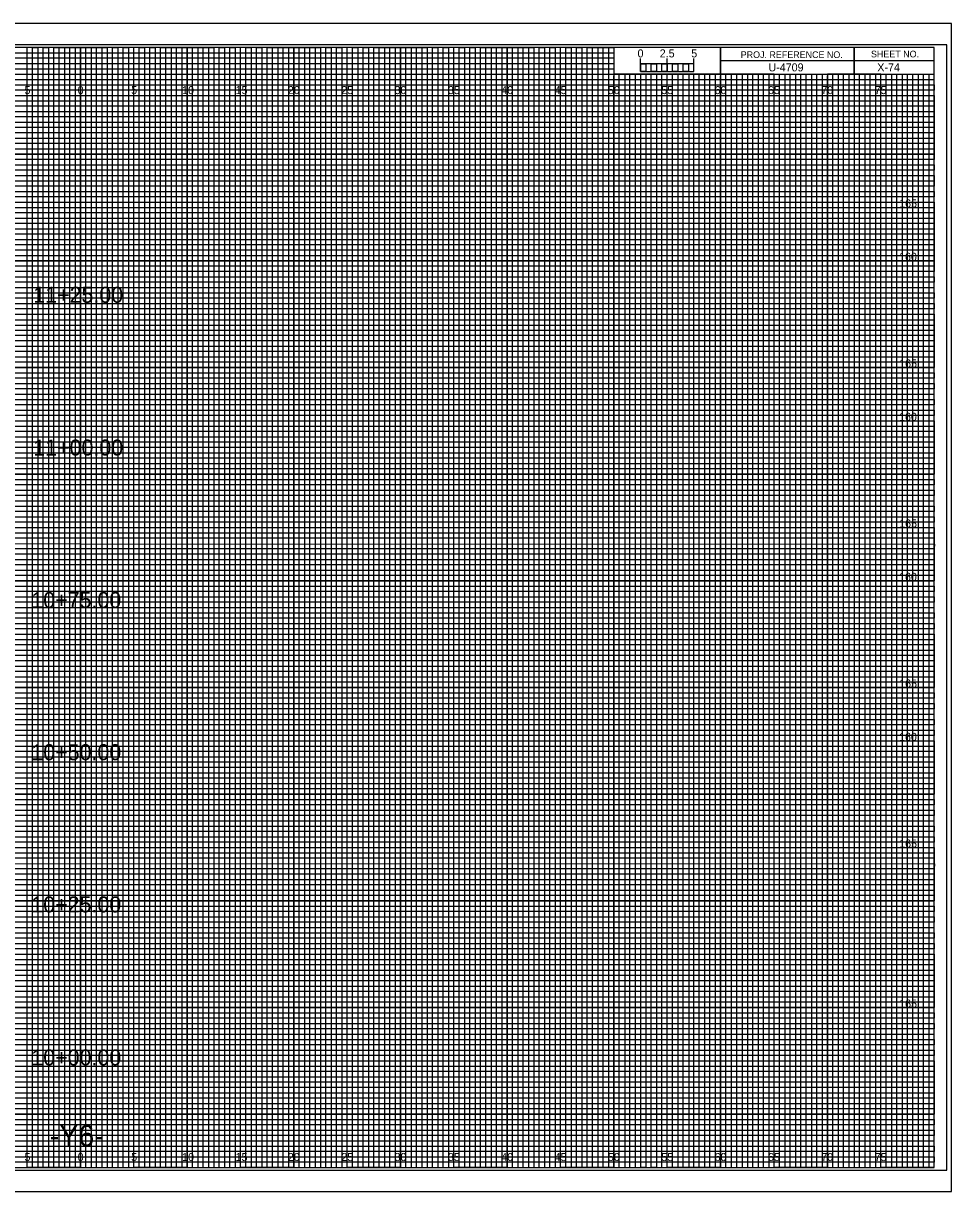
# Model space of a CAD drawing. Extents: x -7 to 162, y -2 to 107.
# Drawn here: x 74.6 to 161.7, y -2.3 to 107.3 of the extents above; entities that cross this region are included whole.
import ezdxf

# ---------------------------------------------------------------- set-up
doc = ezdxf.new("R2010")
doc.units = 0
for name, color, linetype in [('Prop CMT Conc Surface', 7, 'Continuous'), ('Prop CMT Pvmt Wedge Surface 1', 7, 'Continuous'), ('Prop CMT Pvmt Wedge Surface 2', 7, 'Continuous'), ('Prop XS Alignment Label', 7, 'Continuous'), ('Prop XS Bar Scale Labels', 7, 'Continuous'), ('Prop XS Ditch Standard Text', 7, 'Continuous'), ('Prop XS Elevation Labels', 7, 'Continuous'), ('Prop XS Hydro Elevations', 7, 'Continuous'), ('Prop XS Project Number', 7, 'Continuous'), ('Prop XS SE Text', 7, 'Continuous'), ('Prop XS Sheet Number', 7, 'Continuous'), ('Prop XS Side Slope Text', 7, 'Continuous'), ('Prop XS Station Labels', 7, 'Continuous'), ('Sheet Cutting Line CELL', 7, 'Continuous'), ('Sheet DOT Grid CELL', 7, 'Continuous'), ('Sheet Plot Border Inside CELL', 7, 'Continuous'), ('Sheet Plot Border Outside CELL', 7, 'Continuous')]:
    doc.layers.add(name, color=color, linetype=linetype)

msp = doc.modelspace()

# ---------------------------------------------------------------- linework, layer by layer
at = {"layer": 'Prop CMT Pvmt Wedge Surface 1'}
for p, q in [((132.5, 102.75), (132.5, 103.95)), ((132.5, 103.45), (132.5, 103.95)), ((135, 102.75), (135, 103.95)), ((137.5, 102.75), (137.5, 103.95)), ((137.5, 103.45), (137.5, 103.95))]:
    msp.add_line(p, q, dxfattribs=at)
for points in [[(137.5, 103.45), (132.5, 103.45), (132.5, 102.75), (137.5, 102.75)], [(132.5, 103.45), (133, 103.45), (133, 102.75), (132.5, 102.75)], [(133.5, 103.45), (134, 103.45), (134, 102.75), (133.5, 102.75)], [(134.5, 103.45), (135, 103.45), (135, 102.75), (134.5, 102.75)], [(135.5, 103.45), (136, 103.45), (136, 102.75), (135.5, 102.75)], [(136.5, 103.45), (137, 103.45), (137, 102.75), (136.5, 102.75)]]:
    msp.add_lwpolyline(points, close=True, dxfattribs=at)
at = {"layer": 'Prop CMT Pvmt Wedge Surface 2'}
for p, q in [((133.5, 102.5), (133, 102.5)), ((133, 102.5), (133, 0)), ((133.5, 0), (133.5, 102.5)), ((134.5, 102.5), (134, 102.5)), ((134, 102.5), (134, 0)), ((134.5, 0), (134.5, 102.5)), ((133, 0), (132.5, 0)), ((134, 0), (133.5, 0))]:
    msp.add_line(p, q, dxfattribs=at)
for points in [[(75, 0), (75.5, 0), (75.5, 105), (76, 105), (76, 0)], [(76, 0), (76.5, 0), (76.5, 105), (77, 105), (77, 0)], [(77.5, 0), (78, 0), (78, 105), (78.5, 105), (78.5, 0)], [(78.5, 0), (79, 0), (79, 105), (79.5, 105), (79.5, 0)], [(80, 0), (80.5, 0), (80.5, 105), (81, 105), (81, 0)], [(81, 0), (81.5, 0), (81.5, 105), (82, 105), (82, 0)], [(82.5, 0), (83, 0), (83, 105), (83.5, 105), (83.5, 0)], [(83.5, 0), (84, 0), (84, 105), (84.5, 105), (84.5, 0)], [(85, 0), (85.5, 0), (85.5, 105), (86, 105), (86, 0)], [(86, 0), (86.5, 0), (86.5, 105), (87, 105), (87, 0)], [(87.5, 0), (88, 0), (88, 105), (88.5, 105), (88.5, 0)], [(88.5, 0), (89, 0), (89, 105), (89.5, 105), (89.5, 0)], [(90, 0), (90.5, 0), (90.5, 105), (91, 105), (91, 0)], [(91, 0), (91.5, 0), (91.5, 105), (92, 105), (92, 0)], [(92.5, 0), (93, 0), (93, 105), (93.5, 105), (93.5, 0)], [(93.5, 0), (94, 0), (94, 105), (94.5, 105), (94.5, 0)], [(95, 0), (95.5, 0), (95.5, 105), (96, 105), (96, 0)], [(96, 0), (96.5, 0), (96.5, 105), (97, 105), (97, 0)], [(97.5, 0), (98, 0), (98, 105), (98.5, 105), (98.5, 0)], [(98.5, 0), (99, 0), (99, 105), (99.5, 105), (99.5, 0)], [(100, 0), (100.5, 0), (100.5, 105), (101, 105), (101, 0)], [(101, 0), (101.5, 0), (101.5, 105), (102, 105), (102, 0)], [(102.5, 0), (103, 0), (103, 105), (103.5, 105), (103.5, 0)], [(103.5, 0), (104, 0), (104, 105), (104.5, 105), (104.5, 0)], [(105, 0), (105.5, 0), (105.5, 105), (106, 105), (106, 0)], [(106, 0), (106.5, 0), (106.5, 105), (107, 105), (107, 0)], [(107.5, 0), (108, 0), (108, 105), (108.5, 105), (108.5, 0)], [(108.5, 0), (109, 0), (109, 105), (109.5, 105), (109.5, 0)], [(110, 0), (110.5, 0), (110.5, 105), (111, 105), (111, 0)], [(111, 0), (111.5, 0), (111.5, 105), (112, 105), (112, 0)], [(112.5, 0), (113, 0), (113, 105), (113.5, 105), (113.5, 0)], [(113.5, 0), (114, 0), (114, 105), (114.5, 105), (114.5, 0)], [(115, 0), (115.5, 0), (115.5, 105), (116, 105), (116, 0)], [(116, 0), (116.5, 0), (116.5, 105), (117, 105), (117, 0)], [(117.5, 0), (118, 0), (118, 105), (118.5, 105), (118.5, 0)], [(118.5, 0), (119, 0), (119, 105), (119.5, 105), (119.5, 0)], [(120, 0), (120.5, 0), (120.5, 105), (121, 105), (121, 0)], [(121, 0), (121.5, 0), (121.5, 105), (122, 105), (122, 0)], [(122.5, 0), (123, 0), (123, 105), (123.5, 105), (123.5, 0)], [(123.5, 0), (124, 0), (124, 105), (124.5, 105), (124.5, 0)], [(125, 0), (125.5, 0), (125.5, 105), (126, 105), (126, 0)], [(126, 0), (126.5, 0), (126.5, 105), (127, 105), (127, 0)], [(127.5, 0), (128, 0), (128, 105), (128.5, 105), (128.5, 0)], [(128.5, 0), (129, 0), (129, 105), (129.5, 105), (129.5, 0)], [(130, 0), (130.5, 0), (130.5, 102.5), (131.01, 102.5), (131.01, 0)], [(131, 0), (131.5, 0), (131.5, 102.5), (132, 102.5), (132, 0)], [(135, 0), (135.49, 0), (135.49, 102.5), (136, 102.5), (136, 0)], [(136, 0), (136.5, 0), (136.5, 102.5), (137.03, 102.5), (137.03, 0)], [(137.5, 0), (138, 0), (138, 102.5), (138.5, 102.5), (138.5, 0)], [(138.5, 0), (139, 0), (139, 102.5), (139.5, 102.5), (139.5, 0)], [(140, 0), (140.5, 0), (140.5, 102.5), (141, 102.5), (141, 0)], [(141, 0), (141.5, 0), (141.5, 102.5), (142, 102.5), (142, 0)], [(142.5, 0), (143, 0), (143, 102.5), (143.5, 102.5), (143.5, 0)], [(143.5, 0), (144, 0), (144, 102.5), (144.5, 102.5), (144.5, 0)], [(145, 0), (145.5, 0), (145.5, 102.5), (146, 102.5), (146, 0)], [(146, 0), (146.5, 0), (146.5, 102.5), (147, 102.5), (147, 0)], [(147.5, 0), (148, 0), (148, 102.5), (148.5, 102.5), (148.5, 0)], [(148.5, 0), (149, 0), (149, 102.5), (149.5, 102.5), (149.5, 0)], [(150, 0), (150.5, 0), (150.5, 102.5), (151, 102.5), (151, 0)], [(151, 0), (151.5, 0), (151.5, 102.5), (152, 102.5), (152, 0)], [(152.5, 0), (153, 0), (153, 102.5), (153.5, 102.5), (153.5, 0)], [(153.5, 0), (154, 0), (154, 102.5), (154.5, 102.5), (154.5, 0)], [(155, 0), (155.5, 0), (155.5, 102.5), (156, 102.5), (156, 0)], [(156, 0), (156.5, 0), (156.5, 102.5), (157, 102.5), (157, 0)], [(157.5, 0), (158, 0), (158, 102.5), (158.5, 102.5), (158.5, 0)], [(158.5, 0), (159, 0), (159, 102.5), (159.5, 102.5), (159.5, 0)]]:
    msp.add_lwpolyline(points, dxfattribs=at)
at = {"layer": 'Prop XS Ditch Standard Text'}
for p, q in [((0, 104.5), (130, 104.5)), ((130, 104.5), (130, 103.99)), ((130, 103.99), (0, 103.99)), ((0, 103.5), (130, 103.5)), ((130, 102.95), (0, 102.95)), ((130, 103.5), (130, 102.95)), ((0, 102), (160, 102))]:
    msp.add_line(p, q, dxfattribs=at)
for points in [[(0, 101.5), (135, 101.5), (160, 101.5), (160, 101), (0, 101)], [(0, 100.5), (160, 100.5), (160, 99.5), (0, 99.5)], [(0, 99), (160, 99), (160, 98.5), (0, 98.49)], [(0, 98), (160, 98), (160, 97), (0, 97)], [(0, 96.5), (160, 96.5), (160, 96), (0, 96)], [(0, 95.5), (160, 95.5), (160, 94.5), (0, 94.5)], [(0, 94), (160, 94), (160, 93.5), (0, 93.5)], [(0, 93), (160, 93), (160, 92), (0, 92)], [(0, 91.5), (160, 91.5), (160, 91), (0, 91)], [(0, 90.5), (160, 90.5), (160, 89.5), (0, 89.5)], [(0, 89), (160, 89), (160, 88.5), (0, 88.5)], [(0, 88), (160, 88), (160, 86.98), (160, 86.5), (160, 86), (0, 86)], [(0, 87), (160, 87), (160, 86.5), (0, 86.5)], [(0, 85.5), (160, 85.5), (160, 84.5), (0, 84.52)], [(0, 84.52), (160, 84.5), (160, 84), (0, 84)], [(0, 83.5), (160, 83.5), (160, 83), (0, 83)], [(0, 82), (160, 82), (160, 81.5), (0, 81.5)], [(0, 81), (160, 81), (160, 80.5), (0, 80.5)], [(-0.04, 79.45), (160, 79.45), (160, 78.94), (-0.04, 78.94)], [(0, 78.5), (160, 78.5), (160, 78), (0, 78)], [(0, 77), (160, 77), (160, 76.5), (0, 76.5)], [(0, 76), (160, 76), (160, 75.5), (0, 75.5)], [(0, 74.5), (160, 74.5), (160, 74), (0, 74)], [(0, 73.5), (160, 73.5), (160, 73), (0, 73)], [(0, 72), (160, 72), (160, 71.5), (0, 71.5)], [(0, 71), (160, 71), (160, 70.5), (0, 70.5)], [(0, 69.5), (160, 69.5), (160, 68.99), (0, 69)], [(0, 68.5), (160, 68.5), (160, 68), (0, 68)], [(0, 67), (160, 67), (160, 66.5), (0, 66.5)], [(0, 66), (160, 66), (160, 65.5), (0, 65.5)], [(0, 64.5), (160, 64.5), (160, 64), (0, 64)], [(0, 63.5), (160, 63.5), (160, 63), (0, 63)], [(0, 62), (160, 62), (160, 61.5), (0, 61.5)], [(0, 61), (160, 61), (160, 60.5), (0, 60.5)], [(0, 59.5), (160, 59.5), (160, 59), (0, 59)], [(0, 58.5), (160.03, 58.45), (160, 58), (0, 58)], [(0, 57), (160, 57), (160, 56.5), (0, 56.5)], [(0, 56), (160, 56), (160, 55.5), (0, 55.5)], [(0, 54.5), (160, 54.5), (160, 54), (0, 54)], [(0, 53.5), (160, 53.5), (160, 53), (0, 53)], [(0, 52), (160, 52), (160, 51.5), (0, 51.5)], [(0, 51), (160, 51), (160, 50.5), (0, 50.5)], [(0, 49.5), (160, 49.5), (160, 49), (0, 49)], [(0, 48.5), (160, 48.5), (160, 48), (0, 48)], [(0, 47), (160, 47), (160, 46.5), (0, 46.5)], [(0, 46), (160, 46), (160, 45.5), (0, 45.5)], [(0, 44.5), (160, 44.5), (160, 44), (0, 44)], [(0, 43.5), (160, 43.5), (160, 43), (0, 43)], [(0, 42), (160, 42), (160, 41.5), (0, 41.5)], [(0, 41), (160, 41), (160, 40.5), (0, 40.5)], [(0, 39.5), (160, 39.5), (160, 38.99), (0, 39)], [(0, 38.5), (160, 38.5), (160, 38), (0, 38)], [(0, 37), (160, 37), (160, 36.5), (0, 36.5)], [(0, 36), (160, 36), (160, 35.5), (0, 35.5)], [(0, 34.5), (160, 34.5), (160, 34), (0, 34)], [(0, 33.5), (160, 33.5), (160, 33), (0, 33)], [(0, 32), (160, 32), (160, 31.5), (0, 31.5)], [(0, 31), (160, 31), (160, 30.5), (0, 30.5)], [(0, 29.5), (160, 29.5), (160, 29), (0, 29)], [(0, 28.5), (160.03, 28.46), (160, 28), (0, 28)], [(0, 27), (160, 27), (160, 26.5), (0, 26.5)], [(0, 26), (160, 26), (160, 25.5), (0, 25.5)], [(0, 24.5), (160, 24.5), (160, 24), (0, 24)], [(0, 23.5), (160, 23.5), (160, 23), (0, 23)], [(0, 22), (160, 22), (160, 21.5), (0, 21.5)], [(0, 21), (160, 21), (160, 20.5), (0, 20.5)], [(0, 19.5), (160, 19.5), (160, 19), (0, 19)], [(0, 18.5), (160, 18.5), (160, 18), (0, 18)], [(0, 17), (160, 17), (160, 16.5), (0, 16.5)], [(0, 16), (160, 16), (160, 15.5), (0, 15.5)], [(0, 14.5), (160, 14.5), (160, 14), (0, 14)], [(0, 13.5), (160, 13.5), (160, 13), (0, 13)], [(0, 12), (160, 12), (160, 11.5), (0, 11.5)], [(0, 11), (160, 11), (160, 10.5), (0, 10.5)], [(0, 9.5), (160, 9.5), (160, 9), (0, 9)], [(0, 8.5), (160, 8.5), (160, 8), (0, 8)], [(0, 7), (160, 7), (160, 6.5), (0, 6.5)], [(0, 6), (160, 6), (160, 5.5), (0, 5.5)], [(0, 4.5), (160, 4.5), (160, 4), (0, 4)], [(0, 3.5), (160, 3.5), (160, 3), (0, 3)], [(0, 2), (160, 2), (160, 1.5), (0, 1.5)], [(0, 1), (160, 1), (160, 0.5), (0, 0.5)]]:
    msp.add_lwpolyline(points, dxfattribs=at)
at = {"layer": 'Prop XS Hydro Elevations'}
for p, q in [((152.5, 105), (152.5, 102.5)), ((152.5, 102.5), (152.5, 105)), ((160, 103.75), (140, 103.75)), ((140, 103.75), (140, 102.5)), ((140, 102.5), (160, 102.5))]:
    msp.add_line(p, q, dxfattribs=at)
for points in [[(160, 105), (0, 105), (0, 0), (160, 0)], [(140, 105), (130, 105), (130, 102.52), (140, 102.52)], [(160, 105), (140, 105), (140, 102.5), (160, 102.5)]]:
    msp.add_lwpolyline(points, close=True, dxfattribs=at)
at = {"layer": 'Prop XS SE Text'}
for points in [[(72.5, 0), (77.5, 0), (77.5, 105), (82.5, 105), (82.5, 0), (87.5, 0), (87.5, 105), (92.5, 105), (92.5, 0), (97.5, 0), (97.5, 105), (102.5, 105), (102.5, 0), (107.5, 0), (107.5, 105), (112.5, 105), (112.5, 0), (117.5, 0), (117.5, 105), (122.5, 105), (122.5, 0), (127.5, 0), (127.5, 105), (129.97, 105), (130, 105), (130, 102.5), (132.5, 102.5), (132.5, 0), (137.5, 0), (137.5, 102.5), (142.5, 102.5), (142.5, 0), (147.5, 0), (147.5, 102.5), (152.5, 102.5), (152.5, 0), (157.5, 0), (157.5, 102.5)], [(0, 102.5), (137.5, 102.5)], [(0, 92.5), (160, 92.5), (160, 97.5), (0, 97.5)], [(0, 82.5), (160, 82.5), (160, 87.5), (0, 87.5)], [(0, 72.5), (160, 72.5), (160, 77.5), (0, 77.5)], [(0, 62.5), (160, 62.5), (160, 67.5), (0, 67.5)], [(0, 52.5), (160, 52.5), (160, 57.5), (0, 57.5)], [(0, 42.5), (160, 42.5), (160, 47.5), (0, 47.5)], [(0, 32.5), (160, 32.5), (160, 37.5), (0, 37.5)], [(0, 22.5), (160, 22.5), (160, 27.5), (0, 27.5)], [(0, 12.5), (160, 12.5), (160, 17.5), (0, 17.5)], [(0, 2.5), (160, 2.5), (160, 7.5), (0, 7.5)]]:
    msp.add_lwpolyline(points, dxfattribs=at)
at = {"layer": 'Prop XS Side Slope Text'}
for p, q in [((75, 105), (70, 105)), ((75, 0), (75, 105)), ((85, 105), (80, 105)), ((80, 105), (80, 0)), ((85, 0), (85, 105)), ((95, 105), (90, 105)), ((90, 105), (90, 0)), ((95, 0), (95, 105)), ((105, 105), (100, 105)), ((100, 105), (100, 0)), ((105, 0), (105, 105)), ((115, 105), (110, 105)), ((110, 105), (110, 0)), ((115, 0), (115, 105)), ((125, 105), (120, 105)), ((120, 105), (120, 0)), ((125, 0), (125, 105)), ((130, 105), (130, 0)), ((135, 0), (135, 102.5)), ((145, 102.5), (140, 102.5)), ((140, 102.5), (140, 0)), ((145, 0), (145, 102.5)), ((155, 102.5), (150, 102.5)), ((150, 102.5), (150, 0)), ((155, 0), (155, 102.5)), ((80, 0), (75, 0)), ((90, 0), (85, 0)), ((100, 0), (95, 0)), ((110, 0), (105, 0)), ((120, 0), (115, 0)), ((130, 0), (125, 0)), ((140, 0), (135, 0)), ((150, 0), (145, 0)), ((160, 0), (155, 0)), ((160, 0), (160, 0))]:
    msp.add_line(p, q, dxfattribs=at)
for points in [[(0, 100), (160, 100), (160, 95), (0, 95)], [(0, 90), (160, 90), (160, 85), (0, 85)], [(0, 80), (160, 80), (160, 75), (0, 75)], [(0, 70), (160, 70), (160, 65), (0, 65)], [(0, 60), (160, 60), (160, 55), (0, 55)], [(0, 50), (160, 50), (160, 45), (0, 45)], [(0, 40), (160, 40), (160, 35), (0, 35)], [(0, 30), (160, 30), (160, 25), (0, 25)], [(0, 20), (160, 20), (160, 15), (0, 15)], [(0, 10), (160, 10), (160, 5), (0, 5)]]:
    msp.add_lwpolyline(points, dxfattribs=at)
at = {"layer": 'Sheet Cutting Line CELL'}
for p, q in [((161.65, 107.25), (-6.7, 107.25)), ((-6.7, -2.25), (161.65, -2.25))]:
    msp.add_line(p, q, dxfattribs=at)
at = {"layer": 'Sheet DOT Grid CELL'}
for p, q in [((75, 0), (75, 105)), ((80, 0), (80, 105)), ((85, 0), (85, 105)), ((90, 0), (90, 105)), ((95, 0), (95, 105)), ((100, 0), (100, 105)), ((105, 0), (105, 105)), ((110, 0), (110, 105)), ((115, 0), (115, 105)), ((120, 0), (120, 105)), ((125, 0), (125, 105)), ((130, 0), (130, 102.34)), ((135, 0), (135, 102.34)), ((140, 0), (140, 102.34)), ((145, 0), (145, 102.34)), ((150, 0), (150, 102.34)), ((155, 0), (155, 102.34)), ((0, 100), (160, 100)), ((0, 95), (160, 95)), ((0, 90), (160, 90)), ((0, 85), (160, 85)), ((0, 80), (160, 80)), ((0, 75), (160, 75)), ((0, 70), (160, 70)), ((0, 65), (160, 65)), ((0, 60), (160, 60)), ((0, 55), (160, 55)), ((0, 50), (160, 50)), ((0, 45), (160, 45)), ((0, 40), (160, 40)), ((0, 35), (160, 35)), ((0, 30), (160, 30)), ((0, 25), (160, 25)), ((0, 20), (160, 20)), ((0, 15), (160, 15)), ((0, 10), (160, 10)), ((0, 5), (160, 5))]:
    msp.add_line(p, q, dxfattribs=at)
at = {"layer": 'Sheet Plot Border Inside CELL'}
msp.add_lwpolyline([(-5.4, -0.25), (161.2, -0.25), (161.2, 105.25), (-5.4, 105.25)], close=True, dxfattribs=at)
at = {"layer": 'Sheet Plot Border Outside CELL'}
msp.add_lwpolyline([(-6.7, -2.25), (161.65, -2.25), (161.65, 107.25), (-6.7, 107.25)], close=True, dxfattribs=at)

# ---------------------------------------------------------------- texts
at = {"layer": 'Prop CMT Conc Surface'}
for s, p in [('5', (74.74, 100.62)), ('0', (79.73, 100.62)), ('0', (79.73, 100.62)), ('5', (84.74, 100.62)), ('10', (89.52, 100.62)), ('15', (94.53, 100.62)), ('20', (99.43, 100.62)), ('25', (104.44, 100.62)), ('30', (109.43, 100.62)), ('35', (114.44, 100.62)), ('40', (119.43, 100.62)), ('45', (124.44, 100.62)), ('50', (129.43, 100.62)), ('55', (134.44, 100.62)), ('60', (139.43, 100.62)), ('65', (144.44, 100.62)), ('70', (149.43, 100.62)), ('75', (154.44, 100.62)), ('5', (74.74, 0.62)), ('0', (79.73, 0.62)), ('0', (79.73, 0.62)), ('5', (84.74, 0.62)), ('10', (89.52, 0.62)), ('15', (94.53, 0.62)), ('20', (99.43, 0.62)), ('25', (104.44, 0.62)), ('30', (109.43, 0.62)), ('35', (114.44, 0.62)), ('40', (119.43, 0.62)), ('45', (124.44, 0.62)), ('50', (129.43, 0.62)), ('55', (134.44, 0.62)), ('60', (139.43, 0.62)), ('65', (144.44, 0.62)), ('70', (149.43, 0.62)), ('75', (154.44, 0.62))]:
    msp.add_text(s, height=0.75, dxfattribs=at).set_placement(p)
at = {"layer": 'Prop CMT Pvmt Wedge Surface 1'}
msp.add_text('0', height=0.75, dxfattribs=at).set_placement((132.21, 104.06))
at = {"layer": 'Prop XS Alignment Label'}
msp.add_text('-Y6-', height=2, dxfattribs=at).set_placement((77.12, 2))
at = {"layer": 'Prop XS Bar Scale Labels'}
for s, p in [('2.5', (134.29, 104.06)), ('5', (137.24, 104.06))]:
    msp.add_text(s, height=0.75, dxfattribs=at).set_placement(p)
at = {"layer": 'Prop XS Elevation Labels'}
for s, p in [('165', (156.73, 90)), ('160', (156.72, 85)), ('165', (156.73, 75)), ('160', (156.72, 70)), ('165', (156.73, 60)), ('160', (156.72, 55)), ('165', (156.73, 45)), ('160', (156.72, 40)), ('165', (156.73, 30)), ('165', (156.73, 15))]:
    msp.add_text(s, height=0.75, dxfattribs=at).set_placement(p)
at = {"layer": 'Prop XS Hydro Elevations'}
for s, p in [('PROJ. REFERENCE NO.', (141.88, 104)), ('SHEET NO.', (154.09, 104.06))]:
    msp.add_text(s, height=0.625, dxfattribs=at).set_placement(p)
at = {"layer": 'Prop XS Project Number'}
msp.add_text('U-4709', height=0.75, dxfattribs=at).set_placement((144.48, 102.75))
at = {"layer": 'Prop XS Sheet Number'}
msp.add_text('X-74', height=0.75, dxfattribs=at).set_placement((154.68, 102.75))
at = {"layer": 'Prop XS Station Labels'}
for s, p in [('11+25.00', (75.57, 81.06)), ('11+00.00', (75.57, 66.74)), ('10+75.00', (75.39, 52.45)), ('10+50.00', (75.39, 38.19)), ('10+25.00', (75.39, 23.92)), ('10+00.00', (75.39, 9.58))]:
    msp.add_text(s, height=1.5, dxfattribs=at).set_placement(p)

doc.saveas('drawing.dxf')
